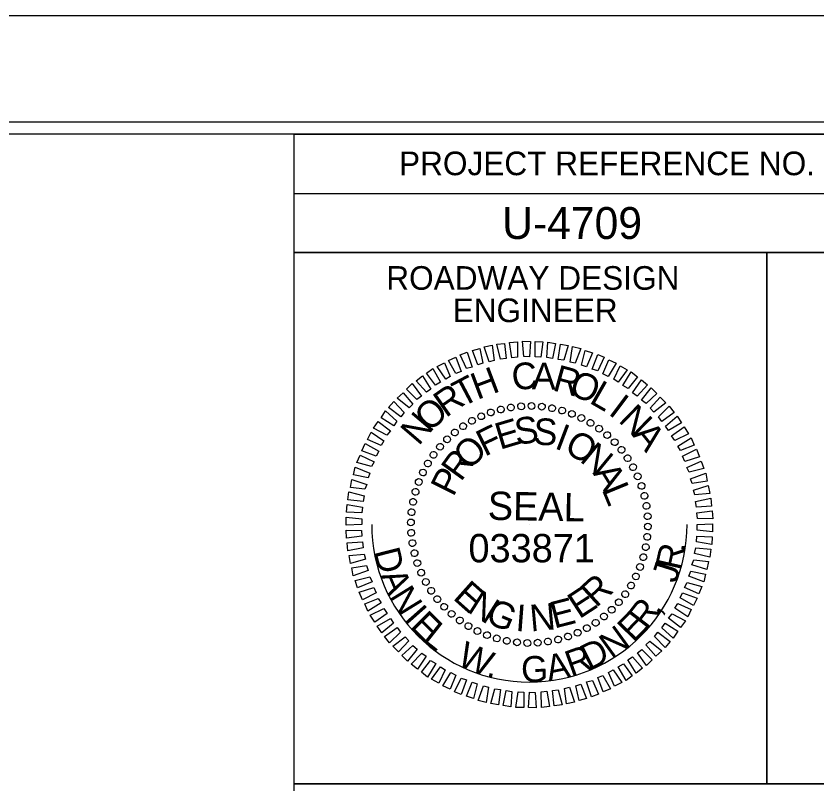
# Model space of a CAD drawing. Extents: x 958711 to 962106, y 831169 to 840840.
# Drawn here: x 960118.9 to 960288.4, y 833331.2 to 833493.8 of the extents above; entities that cross this region are included whole.
import ezdxf

# ---------------------------------------------------------------- set-up
doc = ezdxf.new("R2010")
doc.units = 0
for name, color, linetype in [('Scratch_Level_0', 7, 'Continuous'), ('Sheet Data Field CELL', 7, 'Continuous'), ('Sheet Plot Border Inside CELL', 7, 'Continuous'), ('Sheet Plot Border Outside CELL', 7, 'Continuous'), ('Sheet Professional Seal CELL', 7, 'Continuous'), ('Sheet Profile Grid Minor CELL', 7, 'Continuous'), ('Sheet Sticker Exception Certification CELL', 7, 'Continuous'), ('Sheet Typical CELL', 7, 'Continuous')]:
    doc.layers.add(name, color=color, linetype=linetype)

msp = doc.modelspace()

# ---------------------------------------------------------------- linework, layer by layer
at = {"layer": 'Scratch_Level_0'}
msp.add_arc((960227.55, 833386.13), 33.36, 180, 360, dxfattribs=at)
at = {"layer": 'Sheet Plot Border Inside CELL'}
msp.add_lwpolyline([(960390.3, 833471.32), (958723.8, 833471.32), (958723.8, 832416.22), (960390.3, 832416.22)], close=True, dxfattribs=at)
at = {"layer": 'Sheet Plot Border Outside CELL'}
msp.add_lwpolyline([(960394.8, 833493.77), (958710.8, 833493.77), (958710.8, 832393.77), (960394.8, 832393.77)], close=True, dxfattribs=at)
at = {"layer": 'Sheet Professional Seal CELL'}
for p, q in [((960221.45, 833410.48), (960221.45, 833410.48)), ((960223.65, 833410.88), (960223.65, 833410.88)), ((960225.8, 833411.18), (960225.8, 833411.18)), ((960228, 833411.23), (960228, 833411.23)), ((960230.2, 833411.08), (960230.2, 833411.08)), ((960232.35, 833410.73), (960232.35, 833410.73)), ((960217.35, 833409.08), (960217.35, 833409.08)), ((960219.35, 833409.88), (960219.35, 833409.88)), ((960234.45, 833410.28), (960234.45, 833410.28)), ((960236.55, 833409.58), (960236.55, 833409.58)), ((960238.55, 833408.68), (960238.55, 833408.68)), ((960215.4, 833408.08), (960215.4, 833408.08)), ((960240.5, 833407.68), (960240.5, 833407.68)), ((960211.75, 833405.68), (960211.75, 833405.68)), ((960213.5, 833406.93), (960213.5, 833406.93)), ((960242.3, 833406.43), (960242.3, 833406.43)), ((960210.1, 833404.18), (960210.1, 833404.18)), ((960244.05, 833405.08), (960244.05, 833405.08)), ((960245.6, 833403.58), (960245.6, 833403.58)), ((960208.6, 833402.63), (960208.6, 833402.63)), ((960247.1, 833401.93), (960247.1, 833401.93)), ((960207.25, 833400.88), (960207.25, 833400.88)), ((960248.35, 833400.18), (960248.35, 833400.18)), ((960206, 833399.08), (960206, 833399.08)), ((960205, 833397.13), (960205, 833397.13)), ((960249.5, 833398.28), (960249.5, 833398.28)), ((960204.1, 833395.13), (960204.1, 833395.13)), ((960250.5, 833396.33), (960250.5, 833396.33)), ((960251.3, 833394.33), (960251.3, 833394.33)), ((960203.4, 833393.03), (960203.4, 833393.03)), ((960251.9, 833392.23), (960251.9, 833392.23)), ((960202.95, 833390.93), (960202.95, 833390.93)), ((960252.3, 833390.03), (960252.3, 833390.03)), ((960202.6, 833388.78), (960202.6, 833388.78)), ((960252.6, 833387.88), (960252.6, 833387.88)), ((960202.45, 833386.58), (960202.45, 833386.58)), ((960227.55, 833386.13), (960227.55, 833386.13)), ((960252.65, 833385.68), (960252.65, 833385.68)), ((960202.5, 833384.38), (960202.5, 833384.38)), ((960252.5, 833383.48), (960252.5, 833383.48)), ((960202.8, 833382.23), (960202.8, 833382.23)), ((960203.2, 833380.03), (960203.2, 833380.03)), ((960252.15, 833381.33), (960252.15, 833381.33)), ((960251.7, 833379.23), (960251.7, 833379.23)), ((960203.8, 833377.93), (960203.8, 833377.93)), ((960251, 833377.13), (960251, 833377.13)), ((960204.6, 833375.93), (960204.6, 833375.93)), ((960250.1, 833375.13), (960250.1, 833375.13)), ((960205.6, 833373.98), (960205.6, 833373.98)), ((960249.1, 833373.18), (960249.1, 833373.18)), ((960206.75, 833372.08), (960206.75, 833372.08)), ((960247.85, 833371.38), (960247.85, 833371.38)), ((960208, 833370.33), (960208, 833370.33)), ((960209.5, 833368.68), (960209.5, 833368.68)), ((960245, 833368.08), (960245, 833368.08)), ((960246.5, 833369.63), (960246.5, 833369.63)), ((960211.05, 833367.18), (960211.05, 833367.18)), ((960243.35, 833366.58), (960243.35, 833366.58)), ((960212.8, 833365.83), (960212.8, 833365.83)), ((960214.6, 833364.58), (960214.6, 833364.58)), ((960241.6, 833365.33), (960241.6, 833365.33)), ((960216.55, 833363.58), (960216.55, 833363.58)), ((960237.75, 833363.18), (960237.75, 833363.18)), ((960239.7, 833364.18), (960239.7, 833364.18)), ((960218.55, 833362.68), (960218.55, 833362.68)), ((960220.65, 833361.98), (960220.65, 833361.98)), ((960222.75, 833361.53), (960222.75, 833361.53)), ((960224.9, 833361.18), (960224.9, 833361.18)), ((960231.45, 833361.38), (960231.45, 833361.38)), ((960233.65, 833361.78), (960233.65, 833361.78)), ((960235.75, 833362.38), (960235.75, 833362.38)), ((960227.1, 833361.03), (960227.1, 833361.03)), ((960229.3, 833361.08), (960229.3, 833361.08))]:
    msp.add_line(p, q, dxfattribs=at)
for points in [[(960219.05, 833420.58), (960218, 833423.73), (960219.7, 833424.08), (960220.1, 833420.83)], [(960221.45, 833421.13), (960220.65, 833424.33), (960222.3, 833424.48), (960222.65, 833421.28)], [(960223.85, 833421.43), (960223.3, 833424.63), (960225, 833424.83), (960225.05, 833421.58)], [(960226.35, 833421.68), (960226.1, 833424.93), (960227.75, 833424.88), (960227.55, 833421.63)], [(960228.75, 833421.63), (960228.75, 833424.88), (960230.4, 833424.83), (960229.95, 833421.58)], [(960231.25, 833421.48), (960231.45, 833424.73), (960233.1, 833424.43), (960232.45, 833421.28)], [(960233.65, 833421.08), (960234.1, 833424.28), (960235.75, 833424.03), (960234.85, 833420.93)], [(960214.2, 833419.13), (960212.9, 833422.03), (960214.4, 833422.63), (960215.45, 833419.43)], [(960216.65, 833419.93), (960215.5, 833422.93), (960217.05, 833423.38), (960217.7, 833420.28)], [(960236.2, 833420.53), (960236.7, 833423.78), (960238.4, 833423.38), (960237.25, 833420.28)], [(960238.6, 833419.88), (960239.35, 833422.98), (960240.9, 833422.48), (960239.65, 833419.53)], [(960212, 833418.08), (960210.4, 833420.88), (960211.95, 833421.58), (960213.1, 833418.53)], [(960240.85, 833418.98), (960242, 833422.13), (960243.4, 833421.53), (960242, 833418.63)], [(960243.1, 833418.03), (960244.35, 833420.98), (960245.9, 833420.28), (960244.2, 833417.48)], [(960207.65, 833415.63), (960205.8, 833418.18), (960207.1, 833419.13), (960208.75, 833416.23)], [(960209.85, 833416.88), (960208, 833419.58), (960209.55, 833420.38), (960210.8, 833417.48)], [(960245.4, 833416.88), (960246.75, 833419.73), (960248.25, 833418.88), (960246.35, 833416.28)], [(960205.75, 833414.13), (960203.6, 833416.53), (960204.95, 833417.58), (960206.7, 833414.78)], [(960247.35, 833415.53), (960249.1, 833418.43), (960250.4, 833417.38), (960248.45, 833414.93)], [(960203.75, 833412.58), (960201.55, 833414.78), (960202.75, 833415.98), (960204.7, 833413.28)], [(960249.4, 833414.03), (960251.25, 833416.78), (960252.55, 833415.68), (960250.35, 833413.33)], [(960202.1, 833410.83), (960199.55, 833412.88), (960200.8, 833414.03), (960202.9, 833411.63)], [(960251.3, 833412.48), (960253.35, 833415.08), (960254.55, 833413.88), (960252.25, 833411.73)], [(960200.35, 833408.93), (960197.75, 833410.88), (960198.85, 833412.18), (960201.05, 833409.83)], [(960253.1, 833410.73), (960255.25, 833413.08), (960256.45, 833411.88), (960253.85, 833409.93)], [(960254.85, 833408.93), (960257.15, 833411.18), (960258.2, 833409.83), (960255.55, 833407.93)], [(960198.85, 833407.03), (960196.15, 833408.73), (960197.1, 833410.18), (960199.5, 833407.98)], [(960256.35, 833406.98), (960258.8, 833409.08), (960259.75, 833407.63), (960256.95, 833406.03)], [(960197.35, 833405.03), (960194.55, 833406.53), (960195.55, 833407.93), (960198.15, 833405.93)], [(960196.15, 833402.88), (960193.3, 833404.13), (960194.05, 833405.68), (960196.75, 833403.83)], [(960257.65, 833404.93), (960260.3, 833406.83), (960261.25, 833405.33), (960258.35, 833403.93)], [(960258.95, 833402.73), (960261.75, 833404.48), (960262.4, 833402.93), (960259.55, 833401.78)], [(960195.15, 833400.58), (960192.05, 833401.73), (960192.8, 833403.28), (960195.65, 833401.68)], [(960259.95, 833400.58), (960262.9, 833402.08), (960263.55, 833400.48), (960260.45, 833399.48)], [(960194.15, 833398.38), (960191.05, 833399.28), (960191.7, 833400.83), (960194.7, 833399.43)], [(960260.85, 833398.23), (960263.9, 833399.53), (960264.45, 833397.98), (960261.35, 833397.18)], [(960193.4, 833395.98), (960190.3, 833396.63), (960190.65, 833398.28), (960193.8, 833397.03)], [(960261.65, 833395.83), (960264.85, 833396.98), (960265.15, 833395.33), (960262, 833394.78)], [(960192.75, 833393.58), (960189.65, 833393.98), (960190, 833395.68), (960193.15, 833394.63)], [(960262.25, 833393.43), (960265.4, 833394.38), (960265.7, 833392.68), (960262.55, 833392.38)], [(960192.35, 833391.03), (960189.15, 833391.33), (960189.35, 833393.03), (960192.6, 833392.23)], [(960262.7, 833391.03), (960265.95, 833391.73), (960266.1, 833390.03), (960262.9, 833389.83)], [(960192.1, 833388.63), (960188.85, 833388.73), (960188.95, 833390.38), (960192.2, 833389.83)], [(960263, 833388.63), (960266.25, 833389.03), (960266.35, 833387.33), (960263.1, 833387.43)], [(960192.05, 833386.13), (960188.8, 833385.98), (960188.8, 833387.68), (960192.05, 833387.33)], [(960192.1, 833383.63), (960188.85, 833383.23), (960188.75, 833384.93), (960192, 833384.83)], [(960263.05, 833386.13), (960266.3, 833386.28), (960266.3, 833384.58), (960263.05, 833384.93)], [(960263, 833383.63), (960266.25, 833383.53), (960266.15, 833381.88), (960262.9, 833382.43)], [(960192.4, 833381.23), (960189.15, 833380.53), (960189, 833382.23), (960192.2, 833382.43)], [(960192.85, 833378.83), (960189.7, 833377.88), (960189.4, 833379.58), (960192.55, 833379.88)], [(960262.75, 833381.23), (960265.95, 833380.93), (960265.75, 833379.23), (960262.5, 833380.03)], [(960262.35, 833378.68), (960265.45, 833378.28), (960265.1, 833376.58), (960261.95, 833377.63)], [(960193.45, 833376.43), (960190.25, 833375.28), (960189.95, 833376.93), (960193.1, 833377.48)], [(960194.25, 833374.03), (960191.2, 833372.73), (960190.65, 833374.28), (960193.75, 833375.08)], [(960261.7, 833376.28), (960264.8, 833375.63), (960264.45, 833373.98), (960261.3, 833375.23)], [(960260.95, 833373.88), (960264.05, 833372.98), (960263.4, 833371.43), (960260.4, 833372.83)], [(960195.15, 833371.68), (960192.2, 833370.18), (960191.55, 833371.78), (960194.65, 833372.78)], [(960259.95, 833371.68), (960263.05, 833370.53), (960262.3, 833368.98), (960259.45, 833370.58)], [(960196.15, 833369.53), (960193.35, 833367.78), (960192.7, 833369.33), (960195.55, 833370.48)], [(960197.45, 833367.33), (960194.8, 833365.43), (960193.85, 833366.93), (960196.75, 833368.33)], [(960258.95, 833369.38), (960261.8, 833368.13), (960261.05, 833366.58), (960258.35, 833368.43)], [(960257.75, 833367.23), (960260.55, 833365.73), (960259.55, 833364.33), (960256.95, 833366.33)], [(960198.75, 833365.28), (960196.3, 833363.18), (960195.35, 833364.63), (960198.15, 833366.23)], [(960256.25, 833365.23), (960258.95, 833363.53), (960258, 833362.08), (960255.6, 833364.28)], [(960200.25, 833363.33), (960197.95, 833361.08), (960196.9, 833362.43), (960199.55, 833364.33)], [(960254.75, 833363.33), (960257.35, 833361.38), (960256.25, 833360.08), (960254.05, 833362.43)], [(960202, 833361.53), (960199.85, 833359.18), (960198.65, 833360.38), (960201.25, 833362.33)], [(960253, 833361.43), (960255.55, 833359.38), (960254.3, 833358.23), (960252.2, 833360.63)], [(960203.8, 833359.78), (960201.75, 833357.18), (960200.55, 833358.38), (960202.85, 833360.53)], [(960251.35, 833359.68), (960253.55, 833357.48), (960252.35, 833356.28), (960250.4, 833358.98)], [(960205.7, 833358.23), (960203.85, 833355.48), (960202.55, 833356.58), (960204.75, 833358.93)], [(960249.35, 833358.13), (960251.5, 833355.73), (960250.15, 833354.68), (960248.4, 833357.48)], [(960207.75, 833356.73), (960206, 833353.83), (960204.7, 833354.88), (960206.65, 833357.33)], [(960247.45, 833356.63), (960249.3, 833354.08), (960248, 833353.13), (960246.35, 833356.03)], [(960209.7, 833355.38), (960208.35, 833352.53), (960206.85, 833353.38), (960208.75, 833355.98)], [(960212, 833354.23), (960210.75, 833351.28), (960209.2, 833351.98), (960210.9, 833354.78)], [(960245.25, 833355.38), (960247.1, 833352.68), (960245.55, 833351.88), (960244.3, 833354.78)], [(960214.25, 833353.28), (960213.1, 833350.13), (960211.7, 833350.73), (960213.1, 833353.63)], [(960216.5, 833352.38), (960215.75, 833349.28), (960214.2, 833349.78), (960215.45, 833352.73)], [(960240.9, 833353.13), (960242.2, 833350.23), (960240.7, 833349.63), (960239.65, 833352.83)], [(960243.1, 833354.18), (960244.7, 833351.38), (960243.15, 833350.68), (960242, 833353.73)], [(960218.9, 833351.73), (960218.4, 833348.48), (960216.7, 833348.88), (960217.85, 833351.98)], [(960221.45, 833351.18), (960221, 833347.98), (960219.35, 833348.23), (960220.25, 833351.33)], [(960233.65, 833351.13), (960234.45, 833347.93), (960232.8, 833347.78), (960232.45, 833350.98)], [(960236.05, 833351.68), (960237.1, 833348.53), (960235.4, 833348.18), (960235, 833351.43)], [(960238.45, 833352.33), (960239.6, 833349.33), (960238.05, 833348.88), (960237.4, 833351.98)], [(960223.85, 833350.78), (960223.65, 833347.53), (960222, 833347.83), (960222.65, 833350.98)], [(960226.35, 833350.63), (960226.35, 833347.38), (960224.7, 833347.43), (960225.15, 833350.68)], [(960228.75, 833350.58), (960229, 833347.33), (960227.35, 833347.38), (960227.55, 833350.63)], [(960231.25, 833350.83), (960231.8, 833347.63), (960230.1, 833347.43), (960230.05, 833350.68)]]:
    msp.add_lwpolyline(points, close=True, dxfattribs=at)
for centre, major_axis in [((960219.38, 833409.85), (-0.234, 0.681)), ((960221.48, 833410.47), (-0.174, 0.699)), ((960223.62, 833410.9), (-0.113, 0.711)), ((960225.8, 833411.15), (-0.05, 0.718)), ((960227.99, 833411.21), (0.013, 0.72)), ((960230.17, 833411.08), (0.075, 0.716)), ((960232.33, 833410.75), (0.137, 0.707)), ((960234.46, 833410.24), (0.198, 0.692)), ((960236.54, 833409.55), (0.258, 0.672)), ((960215.39, 833408.07), (-0.349, 0.63)), ((960217.35, 833409.05), (-0.293, 0.658)), ((960238.54, 833408.68), (0.316, 0.647)), ((960213.52, 833406.93), (-0.403, 0.597)), ((960240.46, 833407.63), (0.371, 0.617)), ((960242.29, 833406.42), (0.423, 0.582)), ((960211.76, 833405.62), (-0.453, 0.56)), ((960244, 833405.06), (0.472, 0.543)), ((960210.13, 833404.17), (-0.5, 0.518)), ((960245.59, 833403.56), (0.518, 0.5)), ((960208.62, 833402.59), (-0.543, 0.472)), ((960247.04, 833401.92), (0.56, 0.453)), ((960207.26, 833400.88), (-0.582, 0.423)), ((960248.34, 833400.16), (0.597, 0.403)), ((960206.05, 833399.05), (-0.617, 0.371)), ((960249.48, 833398.29), (0.63, 0.349)), ((960205.01, 833397.13), (-0.647, 0.316)), ((960250.46, 833396.33), (0.658, 0.293)), ((960204.13, 833395.12), (-0.672, 0.258)), ((960251.26, 833394.3), (0.681, 0.234)), ((960203.44, 833393.05), (-0.692, 0.198)), ((960202.93, 833390.92), (-0.707, 0.137)), ((960251.88, 833392.2), (0.699, 0.174)), ((960252.32, 833390.06), (0.711, 0.113)), ((960202.6, 833388.76), (-0.716, 0.075)), ((960252.57, 833387.88), (0.718, 0.05)), ((960202.47, 833386.57), (-0.72, 0.013)), ((960202.53, 833384.38), (-0.718, -0.05)), ((960252.62, 833385.7), (0.72, -0.013)), ((960252.49, 833383.51), (0.716, -0.075)), ((960202.78, 833382.21), (-0.711, -0.113)), ((960252.17, 833381.35), (0.707, -0.137)), ((960203.21, 833380.07), (-0.699, -0.174)), ((960251.66, 833379.22), (0.692, -0.198)), ((960203.83, 833377.97), (-0.681, -0.234)), ((960204.64, 833375.93), (-0.658, -0.293)), ((960250.96, 833377.15), (0.672, -0.258)), ((960205.61, 833373.97), (-0.63, -0.349)), ((960250.09, 833375.14), (0.647, -0.316)), ((960249.05, 833373.22), (0.617, -0.371)), ((960206.76, 833372.11), (-0.597, -0.403)), ((960247.84, 833371.39), (0.582, -0.423)), ((960208.06, 833370.35), (-0.56, -0.453)), ((960246.48, 833369.68), (0.543, -0.472)), ((960209.51, 833368.71), (-0.518, -0.5)), ((960211.09, 833367.21), (-0.472, -0.543)), ((960244.97, 833368.09), (0.5, -0.518)), ((960212.81, 833365.84), (-0.423, -0.582)), ((960243.33, 833366.64), (0.453, -0.56)), ((960214.63, 833364.64), (-0.371, -0.617)), ((960239.71, 833364.2), (0.349, -0.63)), ((960241.57, 833365.34), (0.403, -0.597)), ((960216.55, 833363.59), (-0.316, -0.647)), ((960218.56, 833362.72), (-0.258, -0.672)), ((960235.71, 833362.42), (0.234, -0.681)), ((960237.75, 833363.22), (0.293, -0.658)), ((960220.63, 833362.03), (-0.198, -0.692)), ((960222.76, 833361.51), (-0.137, -0.707)), ((960224.93, 833361.19), (-0.075, -0.716)), ((960227.11, 833361.06), (-0.013, -0.72)), ((960229.3, 833361.11), (0.05, -0.718)), ((960231.47, 833361.36), (0.113, -0.711)), ((960233.61, 833361.8), (0.174, -0.699))]:
    msp.add_ellipse(centre, major_axis=major_axis, ratio=0.999708, dxfattribs=at)
at = {"layer": 'Sheet Sticker Exception Certification CELL'}
for p, q in [((960177.75, 833307.72), (960177.75, 833331.22)), ((960177.75, 833331.22), (960377.79, 833331.22))]:
    msp.add_line(p, q, dxfattribs=at)
at = {"layer": 'Sheet Typical CELL'}
for p, q in [((960177.75, 833456.22), (960377.8, 833456.22)), ((960277.8, 833443.72), (960277.8, 833331.27))]:
    msp.add_line(p, q, dxfattribs=at)
for points in [[(960377.8, 833468.77), (958877.8, 833468.77), (958877.8, 832418.77), (960377.8, 832418.77)], [(960177.75, 833468.77), (960377.8, 833468.77), (960377.8, 833443.72), (960177.75, 833443.72)], [(960177.75, 833443.72), (960277.8, 833443.72), (960277.8, 833331.22), (960177.75, 833331.22)], [(960277.8, 833443.72), (960377.8, 833443.72), (960377.8, 833331.22), (960277.8, 833331.22)]]:
    msp.add_lwpolyline(points, close=True, dxfattribs=at)

# ---------------------------------------------------------------- texts
at = {"layer": 'Sheet Data Field CELL'}
msp.add_text('U-4709', height=6.75, dxfattribs=at).set_placement((960221.78, 833446.57))
at = {"layer": 'Sheet Professional Seal CELL'}
for s, height, rotation, p in [('C', 5.64, 6.2199, (960224.1, 833414.48)), ('H', 5.64, 20.6195, (960216.5, 833412.48)), ('A', 5.64, 359.0203, (960228.05, 833414.78)), ('R', 5.64, 344.6211, (960232.25, 833414.58)), ('T', 5.64, 27.8198, (960213.25, 833410.83)), ('O', 5.64, 337.4212, (960235.6, 833413.83)), ('R', 5.64, 35.0205, (960209.85, 833408.63)), ('L', 5.64, 330.2209, (960240, 833411.98)), ('O', 5.64, 42.2217, (960206.4, 833405.53)), ('I', 5.64, 323.0201, (960244.05, 833409.58)), ('N', 5.64, 315.8189, (960246.2, 833408.03)), ('N', 5.64, 49.4235, (960204.1, 833402.63)), ('E', 5.64, 16.6111, (960221.3, 833401.93)), ('S', 5.64, 7.2556, (960224.75, 833402.98)), ('S', 5.64, 357.9004, (960228.35, 833403.03)), ('F', 5.64, 25.967, (960218.1, 833400.43)), ('I', 5.64, 339.1896, (960232.65, 833402.33)), ('O', 5.64, 329.8335, (960234.65, 833401.63)), ('A', 5.64, 308.6172, (960249.15, 833405.08)), ('O', 5.64, 44.6812, (960214.8, 833397.48)), ('N', 5.64, 320.4766, (960238, 833399.63)), ('R', 5.64, 54.0397, (960213.05, 833395.03)), ('P', 5.64, 63.3989, (960211.45, 833391.83)), ('A', 5.64, 301.7603, (960240.85, 833397.03)), ('L', 5.64, 292.4008, (960242.8, 833393.58)), ('SEAL', 5.998, 359, (960218.7, 833387.13)), ('R', 5.64, 42.4814, (960241.65, 833368.38)), ('E', 5.64, 318.2769, (960211.15, 833370.48)), ('E', 5.64, 33.1241, (960238.1, 833366.03)), ('N', 5.64, 327.634, (960214.15, 833367.78)), ('G', 5.64, 336.9902, (960217.95, 833365.53)), ('E', 5.64, 14.4118, (960232.8, 833364.08)), ('I', 5.64, 355.7012, (960224.5, 833363.63)), ('N', 5.64, 5.0564, (960227.85, 833363.48))]:
    msp.add_text(s, height=height, rotation=rotation, dxfattribs=at).set_placement(p)
at = {"layer": 'Sheet Profile Grid Minor CELL'}
msp.add_text('033871', height=5.998, dxfattribs=at).set_placement((960214.65, 833378.13))
for s, rotation, p in [('R', 77.3541, (960259.52, 833376.23)), ('.', 84.2805, (960260.48, 833380.16)), ('D', 284.2682, (960194.56, 833380.49)), ('J', 72.4855, (960258.56, 833373.55)), ('A', 293.4128, (960195.87, 833375.32)), ('N', 301.5986, (960197.73, 833370.92)), ('R', 52.3788, (960252.35, 833363.66)), ('I', 311.5304, (960200.81, 833366.01)), ('E', 45.7958, (960249.61, 833360.96)), (',', 59.3052, (960254.88, 833366.81)), ('E', 315.0508, (960202.09, 833364.4)), ('L', 321.6338, (960204.75, 833361.63)), ('N', 35.8641, (960244.94, 833357.54)), ('W', 336.8891, (960212, 833356.49)), ('D', 26.7195, (960240.17, 833355.14)), ('R', 19.793, (960236.34, 833353.84)), ('G', 1.6755, (960225.86, 833352.71)), ('A', 11.6072, (960231.65, 833352.92)), ('.', 348.4952, (960218.28, 833353.97))]:
    msp.add_text(s, height=5.5, rotation=rotation, dxfattribs=at).set_placement(p)
at = {"layer": 'Sheet Typical CELL'}
for s, height, p in [('PROJECT REFERENCE NO.', 5.0001, (960199.95, 833460.07)), ('ROADWAY DESIGN', 5.0001, (960197.25, 833435.82)), ('ENGINEER', 5, (960211.3, 833428.97))]:
    msp.add_text(s, height=height, dxfattribs=at).set_placement(p)

doc.saveas('drawing.dxf')
